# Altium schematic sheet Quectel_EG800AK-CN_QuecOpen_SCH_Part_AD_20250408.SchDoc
size A1
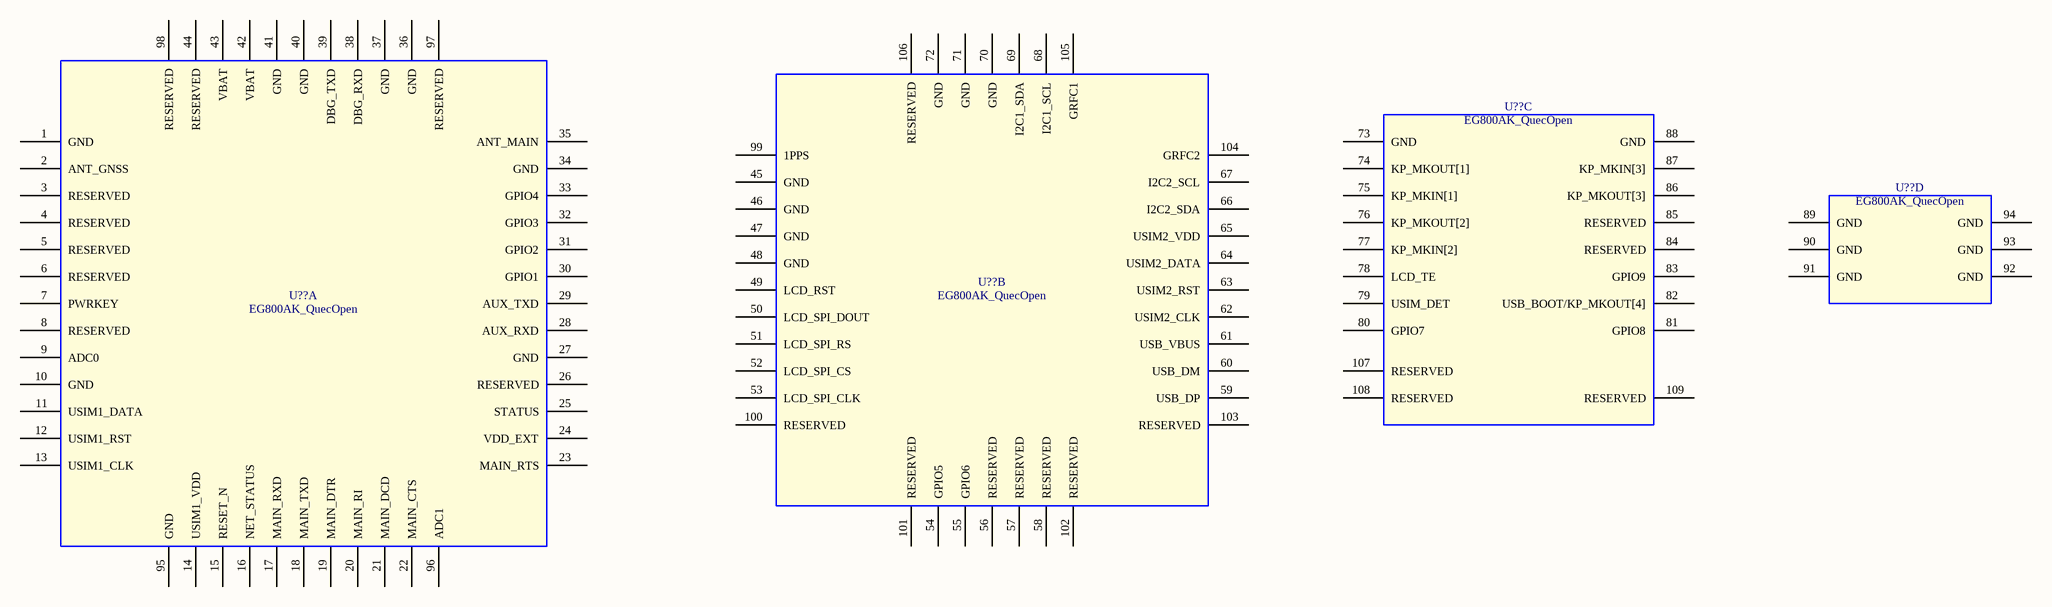
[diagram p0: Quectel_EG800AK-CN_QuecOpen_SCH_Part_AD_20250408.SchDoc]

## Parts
(Parts that share a designator on the sheet are numbered #1, #2 ... from top to bottom, then left to right.)
U??#1  EG800AK_QuecOpen  [EG800AK_QuecOpen]  (part C of 4)
U??#2  EG800AK_QuecOpen  [EG800AK_QuecOpen]  (part D of 4)
U??#3  EG800AK_QuecOpen  [EG800AK_QuecOpen]  (part B of 4)
U??#4  EG800AK_QuecOpen  [EG800AK_QuecOpen]  (part A of 4)

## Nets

Not connected (* = marked no-connect by the designer): U??#1 73(GND) 74(KP_MKOUT[1]) 75(KP_MKIN[1]) 76(KP_MKOUT[2]) 77(KP_MKIN[2]) 78(LCD_TE) 79(USIM_DET) 80(GPIO7) 81(GPIO8) 82(USB_BOOT/KP_MKOUT[4]) 83(GPIO9) 84(RESERVED) 85(RESERVED) 86(KP_MKOUT[3]) 87(KP_MKIN[3]) 88(GND) 107(RESERVED) 108(RESERVED) 109(RESERVED); U??#2 89(GND) 90(GND) 91(GND) 92(GND) 93(GND) 94(GND); U??#3 45(GND) 46(GND) 47(GND) 48(GND) 49(LCD_RST) 50(LCD_SPI_DOUT) 51(LCD_SPI_RS) 52(LCD_SPI_CS) 53(LCD_SPI_CLK) 54(GPIO5) 55(GPIO6) 56(RESERVED) 57(RESERVED) 58(RESERVED) 59(USB_DP) 60(USB_DM) 61(USB_VBUS) 62(USIM2_CLK) 63(USIM2_RST) 64(USIM2_DATA) 65(USIM2_VDD) 66(I2C2_SDA) 67(I2C2_SCL) 68(I2C1_SCL) 69(I2C1_SDA) 70(GND) 71(GND) 72(GND) 99(1PPS) 100(RESERVED) 101(RESERVED) 102(RESERVED) 103(RESERVED) 104(GRFC2) 105(GRFC1) 106(RESERVED); U??#4 1(GND) 2(ANT_GNSS) 3(RESERVED) 4(RESERVED) 5(RESERVED) 6(RESERVED) 7(PWRKEY) 8(RESERVED) 9(ADC0) 10(GND) 11(USIM1_DATA) 12(USIM1_RST) 13(USIM1_CLK) 14(USIM1_VDD) 15(RESET_N) 16(NET_STATUS) 17(MAIN_RXD) 18(MAIN_TXD) 19(MAIN_DTR) 20(MAIN_RI) 21(MAIN_DCD) 22(MAIN_CTS) 23(MAIN_RTS) 24(VDD_EXT) 25(STATUS) 26(RESERVED) 27(GND) 28(AUX_RXD) 29(AUX_TXD) 30(GPIO1) 31(GPIO2) 32(GPIO3) 33(GPIO4) 34(GND) 35(ANT_MAIN) 36(GND) 37(GND) 38(DBG_RXD) 39(DBG_TXD) 40(GND) 41(GND) 42(VBAT) 43(VBAT) 44(RESERVED) 95(GND) 96(ADC1) 97(RESERVED) 98(RESERVED)

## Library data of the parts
U??#1-U??#4 = EG800AK_QuecOpen: EG800AK-CN QuecOpen Module 109PIN 17.7X15.8mm H2.4mm RO; Manufacturer: QUECTEL; Geometry.Height: 2.4mm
